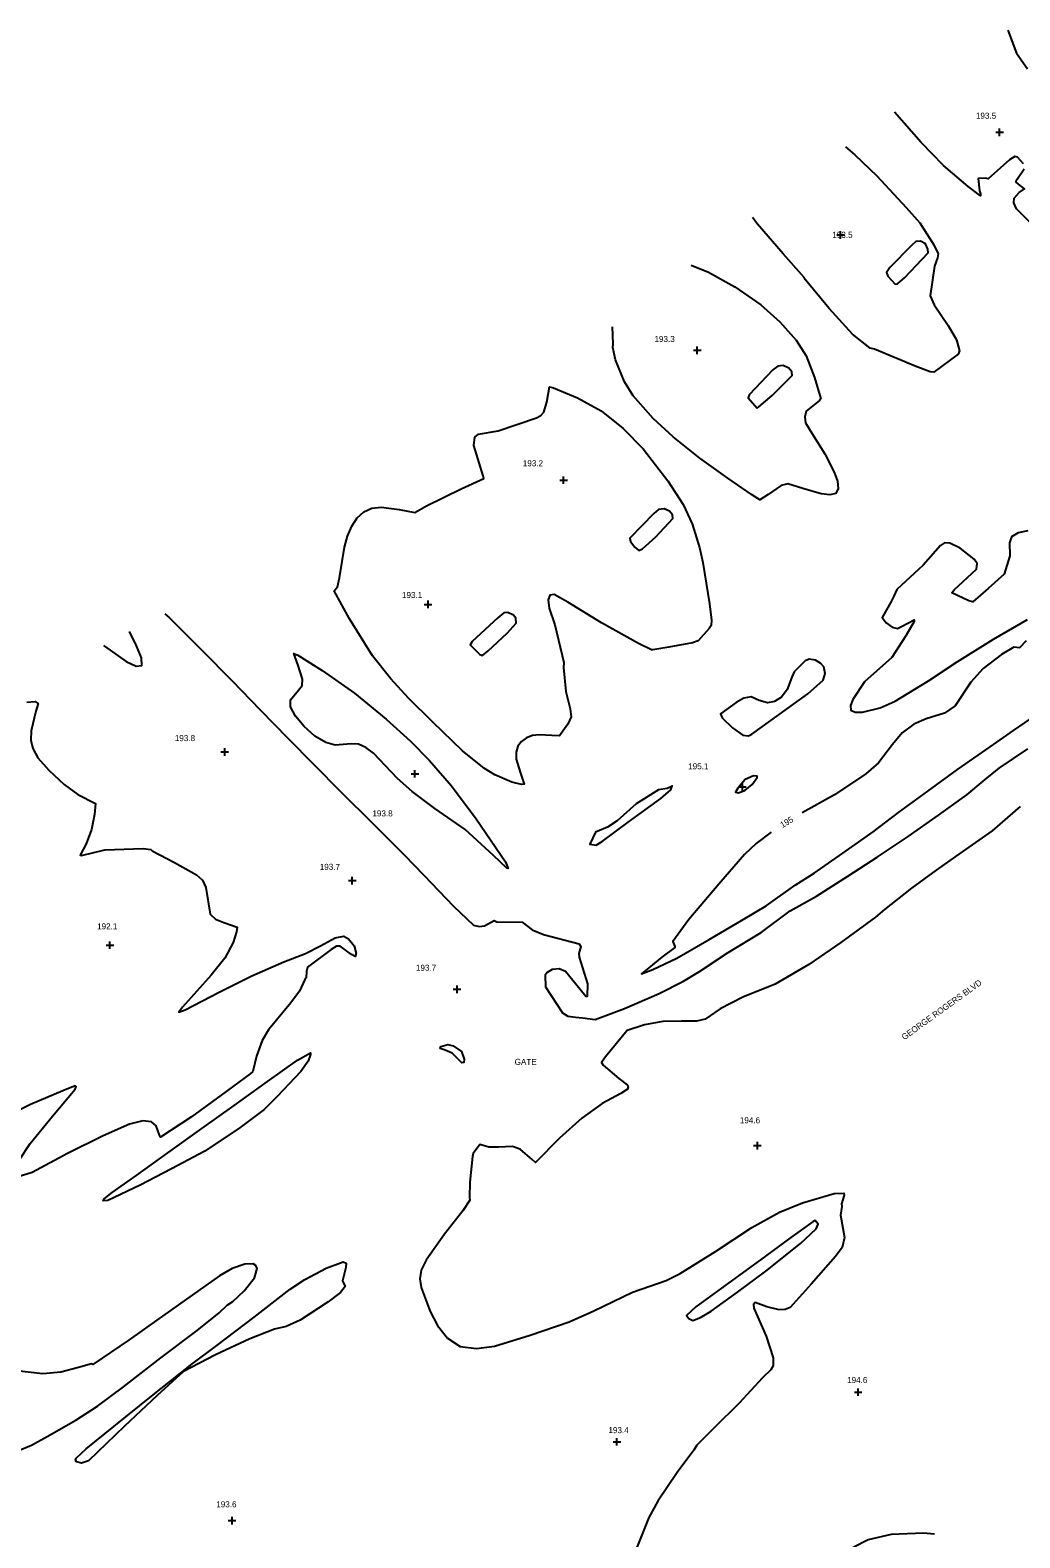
# Model space of a CAD drawing. Extents: x 1475150 to 2003689, y 770235 to 1112803.
# Drawn here: x 1993481.2 to 1993808, y 778593.3 to 779091.1 of the extents above; entities that cross this region are included whole.
import ezdxf

# ---------------------------------------------------------------- set-up
doc = ezdxf.new("R2010")
doc.units = 0
for name, color, linetype in [('RD_DTM_Major1', 7, 'Continuous'), ('RD_DTM_Major1_Lbl', 7, 'Continuous'), ('RD_DTM_Minor1', 7, 'Continuous'), ('RD_DTM_Spot_Elev', 7, 'Continuous'), ('RD_TX_Misc1', 7, 'Continuous')]:
    doc.layers.add(name, color=color, linetype=linetype)

msp = doc.modelspace()

# ---------------------------------------------------------------- linework, layer by layer
at = {"layer": 'RD_DTM_Major1'}
for points in [[(1993810.71, 778925.8), (1993807.49, 778925.14), (1993805.26, 778923.84), (1993804.68, 778921.8), (1993804.78, 778917.59), (1993802.87, 778911.47), (1993797.57, 778906.72), (1993792.5, 778902.41), (1993791.23, 778902.68), (1993785.53, 778905.33), (1993786.39, 778906.36), (1993793.77, 778913.15), (1993793.93, 778915.06), (1993792.99, 778916.41), (1993788.36, 778920.03), (1993784.92, 778921.74), (1993783.15, 778921.84), (1993781.89, 778920.99), (1993776.13, 778914.49), (1993767.43, 778906.43), (1993766.4, 778904.27), (1993765.45, 778902.23), (1993762.57, 778897.21), (1993763.93, 778895.46), (1993765.83, 778894.05), (1993767.66, 778893.61), (1993768.98, 778894.21), (1993773.1, 778896.4), (1993773.17, 778895.92), (1993770.41, 778891.19), (1993765.79, 778884.01), (1993756.78, 778875.9), (1993752.92, 778870.15), (1993752.11, 778868.13), (1993752.25, 778866.63), (1993753.68, 778865.93), (1993756.08, 778865.96), (1993761.93, 778867.4), (1993766.83, 778869.6), (1993777.84, 778876.26), (1993787.31, 778882.51), (1993799.34, 778890.04), (1993810.52, 778896.53)], [(1993810.08, 778889.47), (1993807.95, 778887.17), (1993806.09, 778887.34), (1993801.94, 778885.01), (1993795.97, 778880.32), (1993791.81, 778875.86), (1993786.64, 778868), (1993783.12, 778865.58), (1993777.14, 778863.74), (1993773.03, 778862), (1993769.16, 778859.06), (1993765.97, 778855.3), (1993761.4, 778849.19), (1993757.15, 778845.56), (1993746.85, 778838.66), (1993736.12, 778832.66)], [(1993742.35, 778882.03), (1993740.52, 778883.08), (1993738.45, 778883.48), (1993737.17, 778882.89), (1993733.57, 778879.26), (1993732.77, 778877.5), (1993731.23, 778873.47), (1993729.37, 778870.92), (1993727.01, 778869.41), (1993724.69, 778868.98), (1993721.91, 778869.78), (1993719.32, 778871.01), (1993716.92, 778870.59), (1993714.35, 778869.14), (1993709.17, 778865.43), (1993709.79, 778864.05), (1993713.14, 778860.77), (1993716.53, 778858.31), (1993718.45, 778858.17), (1993719.51, 778858.7), (1993728.61, 778865.11), (1993737.99, 778872), (1993743.1, 778876.46), (1993743.71, 778878.67), (1993743.36, 778880.86), (1993742.35, 778882.03)], [(1993725.9, 778826.36), (1993720.92, 778822.61), (1993717.14, 778818.91), (1993708.62, 778809.19), (1993698.75, 778797.45), (1993693.43, 778790.26), (1993694.12, 778788.51), (1993694.09, 778788.28), (1993689.8, 778785.04), (1993683.08, 778779.55), (1993686.85, 778780.96), (1993694.73, 778784.72), (1993705.41, 778790.83), (1993716.71, 778797.46), (1993724.27, 778801.94), (1993733.88, 778808.86), (1993740.14, 778812.82), (1993749.64, 778819.43), (1993759.62, 778826.45), (1993767.98, 778832.75), (1993777.64, 778839.85), (1993787.48, 778847.01), (1993798.2, 778854.54), (1993806, 778859.88), (1993817.55, 778867.84)], [(1993671.86, 778827.92), (1993667.95, 778826.26), (1993666, 778822.35), (1993668.12, 778822.05), (1993670.15, 778823.21), (1993678.65, 778829.64), (1993689.48, 778837.46), (1993692.74, 778840.32), (1993693.23, 778841.59), (1993692.77, 778841.33), (1993691.57, 778840.72), (1993688.72, 778840.33), (1993681.36, 778835.69), (1993675.08, 778830), (1993671.86, 778827.92)], [(1993714.95, 778840.85), (1993714.18, 778839.48), (1993715, 778839.27), (1993717.26, 778840.06), (1993719.63, 778842.05), (1993721.35, 778844.38), (1993721.33, 778844.83), (1993720.1, 778844.87), (1993717.35, 778843.67), (1993715.46, 778841.47), (1993715.14, 778841.06), (1993714.95, 778840.85)], [(1993779.86, 778594.54), (1993776.19, 778594.9), (1993765.56, 778594.4), (1993757.94, 778592.66), (1993752.98, 778590.1), (1993749.94, 778587.08), (1993746.82, 778581.13), (1993745.34, 778576.33), (1993744.74, 778571.51), (1993745.18, 778569.67), (1993747.91, 778565.66), (1993749.72, 778558.11), (1993751.63, 778549.96), (1993754.47, 778538.13), (1993754.92, 778536.19)]]:
    msp.add_lwpolyline(points, dxfattribs=at)
at = {"layer": 'RD_DTM_Minor1'}
for points in [[(1993804.09, 779091.12), (1993806.91, 779083.56), (1993810.6, 779078.32)], [(1993809.21, 779047.01), (1993807.24, 779049.18), (1993806.34, 779049.42), (1993804.68, 779048.31), (1993797.63, 779042.04), (1993796.7, 779042.23), (1993794.23, 779042.19), (1993794.77, 779038.09), (1993795.1, 779037.07), (1993795.01, 779036.45), (1993791.01, 779039.51), (1993782.87, 779046.47), (1993775.45, 779054), (1993766.63, 779064.09)], [(1993750.51, 779052.65), (1993753.59, 779049.99), (1993760.82, 779042.97), (1993770.54, 779032.56), (1993774.97, 779027.53), (1993779.66, 779020.2), (1993781.08, 779017.3), (1993780.83, 779015.92), (1993779.87, 779013.19), (1993778.42, 779003.43), (1993779.78, 779000.39), (1993784.36, 778993.55), (1993787.17, 778988.87), (1993788.15, 778985.26), (1993787.71, 778984.12), (1993779.6, 778978.23), (1993778.42, 778978.32), (1993773.42, 778980.18), (1993760.06, 778985.76), (1993758.56, 778986.14), (1993752.79, 778990.74), (1993745.12, 778999.23), (1993737.17, 779008.74), (1993736.85, 779009.46), (1993729.88, 779017.32), (1993721.36, 779027.09), (1993719.76, 779029.21)], [(1993812.02, 779027.11), (1993806.95, 779032.14), (1993806.09, 779034.12), (1993806.21, 779035.65), (1993807.82, 779037.57), (1993809.53, 779038.73), (1993807.61, 779040.22), (1993806.72, 779041.02), (1993807.14, 779041.87), (1993809.5, 779045.37)], [(1993765.09, 779012.7), (1993764.02, 779011.08), (1993764.4, 779009.88), (1993766.84, 779007.3), (1993767.68, 779007.4), (1993769.99, 779009.37), (1993777.81, 779017.57), (1993777.7, 779018.86), (1993776.9, 779020.55), (1993775.23, 779021.47), (1993773.74, 779021.35), (1993772.28, 779020.05), (1993765.09, 779012.7)], [(1993699.49, 779013.56), (1993705.21, 779011.26), (1993713.95, 779006.37), (1993722.46, 779000.47), (1993728.83, 778994.77), (1993734.23, 778988.76), (1993737.46, 778983.63), (1993740.28, 778976.39), (1993742.3, 778969.38), (1993741.85, 778968.89), (1993737.52, 778965.37), (1993737.01, 778963.5), (1993737.29, 778961.48), (1993739.37, 778958.07), (1993743.67, 778951.21), (1993746.73, 778945.18), (1993747.78, 778942.22), (1993748.09, 778939.75), (1993747.32, 778938.15), (1993745.29, 778937.64), (1993742.43, 778937.99), (1993736.41, 778939.8), (1993731.47, 778941.36), (1993729.17, 778940.79), (1993724.93, 778937.84), (1993722.23, 778936.06), (1993719.46, 778937.81), (1993711.66, 778943.18), (1993702.39, 778949.83), (1993693.6, 778956.81), (1993686.97, 778962.95), (1993680.4, 778970.38), (1993677.53, 778975), (1993674.52, 778982.29), (1993673.63, 778986.39), (1993673.7, 778987.51), (1993673.51, 778993.13)], [(1993721.28, 778966.33), (1993721.85, 778966.73), (1993726.21, 778970.45), (1993732.82, 778977.12), (1993732.79, 778978.36), (1993731.77, 778979.57), (1993729.85, 778980.41), (1993728.13, 778980.23), (1993726.5, 778979), (1993718.61, 778970.76), (1993718.29, 778969.7), (1993721.28, 778966.33)], [(1993686.87, 778886.56), (1993686.39, 778886.52), (1993682.11, 778888.62), (1993669.93, 778895.48), (1993658.73, 778902.27), (1993654.31, 778904.75), (1993652.81, 778904.61), (1993652.25, 778903), (1993652.59, 778900.25), (1993654.5, 778894.81), (1993657.5, 778882.29), (1993657.35, 778880.66), (1993658.08, 778872.79), (1993659.52, 778867.02), (1993659.86, 778864.36), (1993658.77, 778861.92), (1993656.01, 778858.15), (1993653.52, 778858.2), (1993649.34, 778858.5), (1993647.13, 778858.25), (1993645.11, 778857.5), (1993643.44, 778856.29), (1993642.25, 778854.66), (1993641.66, 778852.68), (1993641.75, 778850.45), (1993643.08, 778846.07), (1993644.36, 778842.12), (1993643.48, 778842.06), (1993640.32, 778842.84), (1993634.66, 778845.24), (1993631.25, 778847.31), (1993624.03, 778853.21), (1993614.24, 778862.61), (1993606.15, 778870.57), (1993600.3, 778876.94), (1993594.3, 778884.57), (1993586.64, 778896.74), (1993581.58, 778906.04), (1993582.69, 778907.37), (1993583.37, 778910.32), (1993584.99, 778920.36), (1993586.01, 778924.05), (1993587.41, 778927.33), (1993589.21, 778930.05), (1993591.42, 778932.07), (1993594.06, 778933.29), (1993597.08, 778933.65), (1993603.07, 778932.81), (1993608.21, 778931.83), (1993612.15, 778934.01), (1993623.6, 778939.64), (1993630.99, 778943.05), (1993630.81, 778944.02), (1993627.77, 778953.93), (1993628.11, 778956.68), (1993629.28, 778957.71), (1993635.75, 778958.77), (1993648.44, 778963.1), (1993649.82, 778963.88), (1993650.81, 778964.98), (1993651.88, 778968.28), (1993652.77, 778973.39), (1993654.09, 778973.05), (1993661.95, 778969.77), (1993669.76, 778965.43), (1993677.1, 778959.62), (1993683.63, 778952.83), (1993691.79, 778942.35), (1993696.85, 778934.53), (1993699.85, 778928.17), (1993702.25, 778920.28), (1993703.31, 778915.3), (1993705.51, 778901.65), (1993706.22, 778896.36), (1993706.06, 778894.59), (1993705.43, 778893.51), (1993701.78, 778889.49), (1993699.89, 778888.86), (1993692.15, 778887.41), (1993686.87, 778886.56)], [(1993680.88, 778920.37), (1993682.27, 778919.35), (1993683.48, 778919.81), (1993687.78, 778923.79), (1993693.42, 778929.87), (1993693.3, 778931.13), (1993692.37, 778932.35), (1993690.57, 778933.1), (1993688.71, 778932.87), (1993687.17, 778931.54), (1993679.28, 778923.43), (1993679.43, 778922.23), (1993680.88, 778920.37)], [(1993525.69, 778898.35), (1993527.25, 778897.03), (1993537.76, 778886.49), (1993547.89, 778876.23), (1993557.16, 778866.69), (1993566.33, 778857.31), (1993574.85, 778848.68), (1993583.8, 778839.68), (1993594.41, 778829.13), (1993604.73, 778818.84), (1993611.19, 778812.14), (1993621.02, 778801.9), (1993627.61, 778795.55), (1993629.51, 778795.11), (1993631.22, 778795.4), (1993634.5, 778797.14), (1993635.36, 778796.74), (1993643.66, 778796.54), (1993647.01, 778794.1), (1993650.7, 778792.56), (1993662.47, 778789.39), (1993663.07, 778788.52), (1993662.46, 778786.26), (1993662.48, 778785.01), (1993665.32, 778776.27), (1993665.12, 778772.06), (1993664.75, 778772.1), (1993662.86, 778774.39), (1993657.98, 778780.34), (1993655.88, 778781.21), (1993653.57, 778780.96), (1993651.97, 778780.01), (1993651.27, 778779.04), (1993651.4, 778775.28), (1993656.99, 778766.64), (1993658.77, 778765.56), (1993661.26, 778765.2), (1993663.63, 778765.03), (1993667.79, 778764.46), (1993677.53, 778768.1), (1993688.96, 778773.01), (1993697.02, 778777.09), (1993702.21, 778780.29), (1993711.67, 778786.57), (1993722.64, 778793.18), (1993732.2, 778800.28), (1993740.91, 778805.16), (1993751.29, 778811.73), (1993760.92, 778818.05), (1993771.15, 778824.93), (1993781.22, 778831.88), (1993790.49, 778838.68), (1993796.63, 778843.68), (1993801.23, 778847.45), (1993810.69, 778853.87)], [(1993638.79, 778892.01), (1993641.72, 778895.33), (1993641.58, 778896.96), (1993640.79, 778897.99), (1993638.94, 778898.83), (1993637.59, 778898.69), (1993635.63, 778897.06), (1993627.13, 778889.23), (1993626.56, 778888.19), (1993629.73, 778884.97), (1993630.56, 778884.69), (1993632.45, 778886.22), (1993638.79, 778892.01)], [(1993505.48, 778887.93), (1993505.72, 778887.7), (1993512.91, 778882.68), (1993516.23, 778881.12), (1993518.14, 778881.32), (1993518.01, 778883.83), (1993516.36, 778887.88), (1993513.97, 778892.56)], [(1993607.37, 778839.69), (1993602.56, 778843.98), (1993594.56, 778852.43), (1993592.12, 778854.26), (1993589.65, 778855.34), (1993587.23, 778855.47), (1993581.97, 778855.06), (1993578.82, 778855.87), (1993575.23, 778858.04), (1993571.68, 778861.15), (1993568.79, 778864.57), (1993567.16, 778867.66), (1993567.18, 778869.96), (1993569.85, 778873.15), (1993570.99, 778874.79), (1993571.19, 778876.85), (1993569.75, 778881.31), (1993568.24, 778885.35), (1993569.62, 778884.73), (1993577.62, 778879.68), (1993588.3, 778872.26), (1993598.81, 778863.66), (1993606.77, 778856.37), (1993613.03, 778850.11), (1993620.38, 778841.61), (1993628.53, 778830.74), (1993638.22, 778816.56), (1993639.02, 778814.33), (1993638.6, 778814.44), (1993634.25, 778818.58), (1993624.92, 778827.17), (1993614.8, 778834.14), (1993607.37, 778839.69)], [(1993480.1, 778869.23), (1993482.82, 778869.44), (1993483.83, 778868.83), (1993483.11, 778866.24), (1993481.52, 778859.73), (1993481.48, 778856.72), (1993482.09, 778853.92), (1993483.79, 778850.86), (1993487.4, 778846.74), (1993492.4, 778842.1), (1993496.97, 778838.77), (1993502.75, 778835.8), (1993502.47, 778832.1), (1993501.5, 778827.17), (1993499.7, 778822.48), (1993497.75, 778818.7), (1993498.22, 778818.57), (1993505.88, 778820.5), (1993518.56, 778820.91), (1993521.06, 778820.54), (1993521.47, 778820.14), (1993528.87, 778816.31), (1993536.13, 778812.22), (1993538.17, 778810.41), (1993539.24, 778808.08), (1993540.69, 778799.27), (1993542.39, 778797.61), (1993545.18, 778796.48), (1993549.57, 778794.91), (1993549.37, 778793.39), (1993548.21, 778789.85), (1993545.48, 778784.76), (1993541.03, 778779.07), (1993531.47, 778768.57), (1993530.35, 778766.86), (1993532.43, 778767.64), (1993543.68, 778773.44), (1993554.44, 778778.85), (1993565.01, 778783.51), (1993572.19, 778786.22), (1993577.11, 778788.8), (1993581.89, 778791.38), (1993584.84, 778792), (1993586.33, 778791.04), (1993588.16, 778788.8), (1993588.87, 778786.22), (1993588.5, 778785.3), (1993587.37, 778785.96), (1993583.61, 778788.67), (1993582.35, 778788.62), (1993580.62, 778787.61), (1993572.83, 778781.78), (1993572.44, 778780.34), (1993572.37, 778778.25), (1993571.88, 778777.64), (1993570.2, 778773.81), (1993567.31, 778769.94), (1993559.91, 778761.06), (1993557.84, 778757.53), (1993555.99, 778752.35), (1993554.76, 778747.25), (1993553.9, 778746.51), (1993544.33, 778739.46), (1993534.48, 778732.37), (1993524.23, 778725.62), (1993523.89, 778726.29), (1993522.84, 778729.3), (1993521.24, 778730.69), (1993518.4, 778731.01), (1993514.04, 778729.87), (1993505.37, 778726.07), (1993493.52, 778720.25), (1993481.88, 778713.89), (1993475.82, 778712.01)], [(1993808.13, 778834.76), (1993798.95, 778826.78), (1993786.75, 778818.22), (1993780.4, 778813.8), (1993772.29, 778807.77), (1993763.35, 778800.72), (1993760.37, 778798.23), (1993748.92, 778789.88), (1993738.41, 778782.63), (1993727.26, 778776.08), (1993716.59, 778771.84), (1993709.07, 778767.93), (1993704.07, 778764.59), (1993701.26, 778763.9), (1993696.28, 778763.92), (1993690.14, 778763.79), (1993684.13, 778762.66), (1993678.41, 778760.78), (1993671.25, 778752.12), (1993669.93, 778750.24), (1993670.44, 778749.33), (1993675.63, 778744.98), (1993678.42, 778742.87), (1993678.7, 778742.2), (1993678.5, 778741.5), (1993676.25, 778740.02), (1993670.15, 778736.73), (1993663.43, 778731.92), (1993655.97, 778725.26), (1993648.1, 778717.29), (1993647.02, 778718.26), (1993643.15, 778721.54), (1993642.34, 778721.84)], [(1993620.58, 778753.33), (1993618.25, 778754.3), (1993616.65, 778754.85), (1993616.81, 778755.49), (1993619.12, 778756.24), (1993620.93, 778755.73), (1993623.64, 778753.92), (1993624.59, 778751.4), (1993624.38, 778750.3), (1993623.8, 778750.17), (1993620.58, 778753.33)], [(1993508.32, 778707.31), (1993516.43, 778713.11), (1993526.7, 778720.42), (1993537.92, 778728.44), (1993548.54, 778736.08), (1993559.63, 778743.96), (1993569.5, 778750.98), (1993573.75, 778753.5), (1993573.83, 778752.88), (1993573.02, 778750.7), (1993570.55, 778747.25), (1993562.81, 778739.04), (1993558.48, 778734.78), (1993550.57, 778728.74), (1993538.94, 778720.94), (1993527.88, 778715.17), (1993517.55, 778709.78), (1993506.84, 778704.7), (1993505.33, 778704.56), (1993505.68, 778705.26), (1993508.32, 778707.31)], [(1993477.56, 778717.96), (1993481.23, 778723.51), (1993488.61, 778732.58), (1993496.06, 778741.44), (1993496.46, 778742.35), (1993496.04, 778742.57), (1993492, 778740.95), (1993481.37, 778736.34), (1993469.01, 778730.3)], [(1993642.34, 778721.84), (1993640.52, 778722.52), (1993635.87, 778722.34), (1993632.68, 778722.34), (1993629.74, 778723.22), (1993627.46, 778720.24), (1993627.29, 778719.26), (1993626.41, 778710.7), (1993626.32, 778705.65), (1993626.42, 778704.77), (1993624.13, 778701.32), (1993618.03, 778693.56), (1993611.95, 778684.97), (1993610.39, 778681.68), (1993609.92, 778678.85), (1993610.37, 778675.95), (1993613.28, 778668.06), (1993615.71, 778663.38), (1993618.99, 778659.25), (1993623.27, 778656.52), (1993628.61, 778655.77), (1993634.58, 778656.59), (1993646.3, 778660.21), (1993659.24, 778664.61), (1993667.41, 778668.25), (1993680.17, 778674.39), (1993691.3, 778678.29), (1993695.89, 778680.54), (1993707.57, 778687.89), (1993719.51, 778695.81), (1993728.65, 778700.89), (1993736.22, 778703.94), (1993746.78, 778707.05), (1993749.97, 778707.1), (1993750.08, 778706.47), (1993749.14, 778703.57), (1993749.21, 778702.75), (1993748.85, 778699.8), (1993750.17, 778692.44), (1993749.39, 778689.2), (1993747.2, 778686.22), (1993739.12, 778677.02), (1993732.24, 778669.36), (1993730.52, 778668.67), (1993728.52, 778668.6), (1993724.49, 778669.59), (1993720.68, 778671), (1993720.11, 778670.31), (1993720.17, 778669.16), (1993724.27, 778659.9), (1993726.58, 778652.79), (1993726.59, 778650.07), (1993725.77, 778648.77), (1993723.03, 778646.11), (1993715.4, 778637.81), (1993707.07, 778629.64), (1993701.4, 778623.94), (1993700.36, 778622.24), (1993694.91, 778614.9), (1993688.51, 778605.38), (1993685.52, 778600), (1993681.34, 778589.53)], [(1993700.99, 778669.54), (1993697.96, 778666.74), (1993698.72, 778665.7), (1993700, 778665.08), (1993702.59, 778666.08), (1993706.09, 778668.15), (1993714.8, 778674.43), (1993724.15, 778681.37), (1993735.62, 778690.47), (1993740.82, 778695.37), (1993741.4, 778696.84), (1993740.44, 778698.08), (1993739.83, 778697.73), (1993732.45, 778692.47), (1993722.37, 778685.14), (1993711.93, 778677.55), (1993700.99, 778669.54)], [(1993476.02, 778621.61), (1993481.71, 778623.92), (1993486.8, 778626.73), (1993496.25, 778632.2), (1993503.47, 778636.75), (1993511.99, 778643.18), (1993524.4, 778652.79), (1993536.36, 778661.76), (1993543.63, 778667.59), (1993546.23, 778670.1), (1993548.13, 778671.33), (1993551.84, 778674.86), (1993555.25, 778679.14), (1993556.18, 778682.28), (1993555.74, 778683.24), (1993554.83, 778683.78), (1993552.07, 778683.72), (1993547.87, 778682.28), (1993543.72, 778679.83), (1993534.75, 778673.48), (1993523.06, 778665.21), (1993513.86, 778658.63), (1993501.91, 778650.49), (1993501.48, 778650.74), (1993497.19, 778649.52), (1993491.39, 778647.98), (1993485.43, 778647.43), (1993476.73, 778648.41)], [(1993571.93, 778678.6), (1993578.92, 778682.4), (1993584.62, 778684.49), (1993585.57, 778683.96), (1993585.47, 778682.61), (1993584.39, 778678.19), (1993585.19, 778676.25), (1993583.68, 778674.32), (1993579.64, 778671.18), (1993570.35, 778665.13), (1993565.8, 778663.06), (1993561.92, 778662.2), (1993553.78, 778659.04), (1993542.41, 778653.71), (1993531.81, 778648.27), (1993523.17, 778640.29), (1993512.39, 778630.18), (1993500.43, 778618.78), (1993498.21, 778617.93), (1993496.54, 778618.45), (1993496.2, 778618.99), (1993496.39, 778619.66), (1993499.66, 778622.64), (1993508.83, 778630.03), (1993521.33, 778640.07), (1993534.62, 778650.61), (1993542.82, 778656.82), (1993555.16, 778666.2), (1993567.08, 778675.37), (1993571.93, 778678.6)]]:
    msp.add_lwpolyline(points, dxfattribs=at)
at = {"layer": 'RD_DTM_Spot_Elev'}
for p, q in [((1993800.09, 779057.41), (1993802.59, 779057.41)), ((1993801.34, 779056.16), (1993801.34, 779058.66)), ((1993748.86, 779022.26), (1993748.86, 779024.76)), ((1993747.61, 779023.51), (1993750.11, 779023.51)), ((1993700.27, 778985.41), (1993702.77, 778985.41)), ((1993701.52, 778984.16), (1993701.52, 778986.66)), ((1993656.13, 778942.53), (1993658.63, 778942.53)), ((1993657.38, 778941.28), (1993657.38, 778943.78)), ((1993611.38, 778901.5), (1993613.88, 778901.5)), ((1993612.63, 778900.25), (1993612.63, 778902.75)), ((1993544.22, 778852.79), (1993546.72, 778852.79)), ((1993545.47, 778851.54), (1993545.47, 778854.04)), ((1993607.03, 778845.56), (1993609.53, 778845.56)), ((1993608.28, 778844.31), (1993608.28, 778846.81)), ((1993715.19, 778841.3), (1993717.69, 778841.3)), ((1993716.44, 778840.05), (1993716.44, 778842.55)), ((1993586.35, 778810.33), (1993588.85, 778810.33)), ((1993587.6, 778809.08), (1993587.6, 778811.58)), ((1993506.33, 778789), (1993508.83, 778789)), ((1993507.58, 778787.75), (1993507.58, 778790.25)), ((1993622.19, 778773.18), (1993622.19, 778775.68)), ((1993620.94, 778774.43), (1993623.44, 778774.43)), ((1993720.13, 778722.83), (1993722.63, 778722.83)), ((1993721.38, 778721.58), (1993721.38, 778724.08)), ((1993753.39, 778641.39), (1993755.89, 778641.39)), ((1993754.64, 778640.14), (1993754.64, 778642.64)), ((1993675, 778623.75), (1993675, 778626.25)), ((1993673.75, 778625), (1993676.25, 778625)), ((1993546.65, 778598.99), (1993549.15, 778598.99)), ((1993547.9, 778597.74), (1993547.9, 778600.24))]:
    msp.add_line(p, q, dxfattribs=at)

# ---------------------------------------------------------------- texts
at = {"layer": 'RD_DTM_Major1_Lbl'}
msp.add_text('195', height=2, rotation=31.0495, dxfattribs=at).set_placement((1993729.66, 778827.63))
at = {"layer": 'RD_DTM_Spot_Elev'}
for s, p in [('193.5', (1993793.53, 779061.87)), ('193.5', (1993746.12, 779022.55)), ('193.3', (1993687.39, 778988.14)), ('193.2', (1993643.9, 778947.12)), ('193.1', (1993604, 778903.61)), ('193.8', (1993528.98, 778856.37)), ('195.1', (1993698.52, 778847.05)), ('193.8', (1993594.24, 778831.51)), ('193.7', (1993576.85, 778813.85)), ('192.1', (1993503.32, 778794.21)), ('193.7', (1993608.61, 778780.54)), ('194.6', (1993715.58, 778730.19)), ('194.6', (1993751.01, 778644.41)), ('193.4', (1993672.19, 778627.87)), ('193.6', (1993542.67, 778603.39))]:
    msp.add_text(s, height=2, dxfattribs=at).set_placement(p)
at = {"layer": 'RD_TX_Misc1'}
msp.add_text('GEORGE ROGERS BLVD', height=2, rotation=35.8584, dxfattribs=at).set_placement((1993769.91, 778757.56))
msp.add_text('GATE', height=2, dxfattribs=at).set_placement((1993641.21, 778749.46))

doc.saveas('drawing.dxf')
